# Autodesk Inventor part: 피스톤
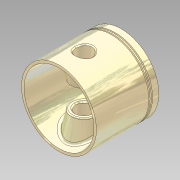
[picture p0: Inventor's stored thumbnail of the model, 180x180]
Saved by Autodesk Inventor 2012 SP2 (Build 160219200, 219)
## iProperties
Manager: KYOUNG IL JANG
Company: 한국ATC센터
Created: 2012-10
Part Number: 피스톤
Document SubType Name: Modeling
Density: 1 g/cm^3
Checked By: KYOUNG IL JANG
Vendor: CBT Solutions
Designer: KYOUNG IL JANG
Material: 기본값
Author: KYOUNG IL JANG
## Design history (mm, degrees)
sketch "스케치1"
  geometry: L1 (0, 0)-(0, 50); L2 (0, 50)-(30, 50); L3 (30, 50)-(30, 45); L4 (30, 45)-(28, 45); L5 (28, 45)-(28, 44); L6 (28, 44)-(30, 44); L7 (30, 44)-(30, 43); L8 (30, 43)-(28, 43); L9 (28, 43)-(28, 42); L10 (28, 42)-(30, 42); L11 (30, 42)-(30, 0); L12 (30, 0)-(28, 0); L13 (28, 0)-(23, 45); L14 (23, 45)-(0, 45)
  constraints: 28 end point, 10 parallel, 5 collinear, 2 perpendicular, 2 point on line, 1 vertical
  dimensions: "d0" = 50 distance of L1.start L1.end; "d1" = 60 diameter of L3 L1; "d2" = 5 distance between parallel lines of L2 L14; "d3" = 2 distance of L11.end L12.end; "d5" = 5 distance of L2.end L3.end; "d6" = 1 distance of L4.end L5.end; "d7" = 2 distance of L9.end L10.end; "d26" = 46 diameter of L13.end L1
revolve "회전1" sketch "스케치1" stored, may be unused: angle "d8" = 90 deg
node "작업 평면1"
sketch "스케치2"
  geometry: L1 (-28, 0)-(28, 0) reference; C1 r 10 at (0, 20); C2 r 6.5 at (0, 20); 1 further point
  constraints: 2 centre point, 1 coincident, 1 vertical alignment
  dimensions: "d10" = 20 diameter of C1; "d13" = 20 distance from line of C1.centre L1; "d14" = 13 diameter of C2
extrude "돌출1" join sketch "스케치2" stored distance "d11" = 10; taper "d12" = 12 deg
extrude "돌출2" cut sketch "스케치2" stored distance "d15" = 10; taper "d16" = 0 deg
fillet "모깎기1" dims "d17" = 2, "d21" = 3
chamfer "모따기1" distance "d18" = 1; stored, may be unused: second distance "d19" = 2, angle "d20" = 45 deg
chamfer "모따기2" distance "d22" = 1; stored, may be unused: second distance "d23" = 2, angle "d24" = 45 deg
fillet "모깎기2" dims "d25" = 1
node "솔리드1"
mirror "대칭1"
